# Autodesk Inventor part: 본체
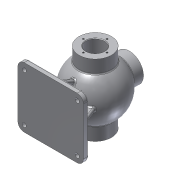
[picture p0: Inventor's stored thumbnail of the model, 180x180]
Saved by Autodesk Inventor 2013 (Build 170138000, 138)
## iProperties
Created: 2018-06
Part Number: 본체
Material: 알루미늄 6061
Document SubType Name: Modeling
Designer: Administrator
Density: 2.71 g/cm^3
Mass: 1509.59 g
Surface Area: 1153.86 cm^2
Volume: 557.044 cm^3
Author: Administrator
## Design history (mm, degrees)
sketch "스케치2"
  geometry: L1 (0, 103.075)-(0, -103.075); A1 r 53 centre (0, 0) between (0, -53) and (0, 53); 2 further points
  constraints: 2 coincident, 2 end point, 2 point on circle, 2 point on line, 1 centre point, 1 midpoint, 1 vertical
  dimensions: "d0" = 106 diameter of A1
revolve "회전1" sketch "스케치2" stored, may be unused: angle "d1" = 90 deg
node "작업 평면1"
sketch "스케치4"
  geometry: C1 r 31 at (0, 0); 1 further point
  constraints: 1 centre point, 1 coincident
  dimensions: "d3" = 62 diameter of C1
extrude "돌출1" join sketch "스케치4" distance "d4" = 136; taper "d5" = 0 deg
sketch "스케치5"
  geometry: L1 (0, -49.435)-(0, 49.435); A1 r 43 centre (0, 0) between (0, -43) and (0, 43); 2 further points
  constraints: 2 coincident, 2 end point, 2 point on circle, 2 point on line, 1 centre point, 1 midpoint, 1 vertical
  dimensions: "d6" = 86 diameter of A1
revolve "회전2" sketch "스케치5" stored, may be unused: angle "d7" = 90 deg
sketch "스케치6"
  geometry: C1 r 31 at (0, 0) reference; C2 r 17.5 at (0, 0)
  constraints: 1 centre point, 1 coincident
  dimensions: "d8" = 35 diameter of C2
extrude "돌출2" cut sketch "스케치6" stored distance "d9" = 136; taper "d10" = 0 deg
node "작업 평면2"
sketch "스케치7"
  geometry: L1 (62.5, -57.5)-(-62.5, -57.5); L2 (-62.5, -57.5)-(-62.5, 57.5); L3 (-62.5, 57.5)-(62.5, 57.5); L4 (62.5, 57.5)-(62.5, -57.5); L5 (62.5, -57.5)-(-62.5, 57.5); L6 (-62.5, -57.5)-(62.5, 57.5); 1 further point
  constraints: 12 end point, 2 midpoint, 2 parallel, 1 horizontal, 1 perpendicular
  dimensions: "d12" = 125 distance of L2.end L3.end; "d13" = 115 distance of L1.end L2.end
extrude "돌출3" join sketch "스케치7" distance "d14" = 10; taper "d15" = 0 deg
fillet "모깎기1" dims "d16" = 12
sketch "스케치8"
  geometry: L1 (-31.053, 29.744)-(-75, 47.5); L2 (-75, 47.5)-(-75, -47.5); L3 (-75, -47.5)-(-31.053, -29.744); L4 (-75, -57.5)-(-85, -57.5) reference; L5 (-85, 57.5)-(-75, 57.5) reference; L6 (-75, -45.5)-(-75, 45.5) reference; A1 r 43 centre (0, 0) between (-31.053, 29.744) and (-31.053, -29.744); 2 further points
  constraints: 6 end point, 2 midpoint, 2 point on circle, 1 centre point, 1 coincident, 1 vertical
  dimensions: "d18" = 86 diameter of A1; "d20" = 10 distance from line of L4 L2.end; "d21" = 10 distance from line of L5 L1.end; "d22" = 22 deg angle of L5 L1; "d23" = 22 deg angle of L4 L3
extrude "돌출4" join sketch "스케치8" stored distance "d24" = 8; taper "d25" = 0 deg
sketch "스케치9"
  geometry: L1 (-52.5, -75)-(-42.423, -50.06); L2 (-62.5, -75)-(-62.5, -85) reference; L3 (-50.5, -75)-(50.5, -75) reference; 1 further point
  constraints: 2 end point, 1 point on line
  dimensions: "d26" = 10 distance from line of L2 L1.start; "d27" = 22 deg angle of L2 L1
feature "리브1" sketch "스케치9" dims "d28" = 1, "d29" = 8, "d30" = 0, "d31" = 0, "d32" = 1, "d33" = 1
node "작업 평면3"
sketch "스케치11"
  geometry: C1 r 27 at (0, 0); 1 further point
  constraints: 1 centre point, 1 coincident
  dimensions: "d44" = 54 diameter of C1
extrude "돌출5" join sketch "스케치11" stored distance "d45" = 8; taper "d46" = 0 deg
sketch "스케치12"
  geometry: C1 r 27 at (0, 0) reference; C2 r 13 at (0, 0)
  constraints: 1 centre point, 1 coincident
  dimensions: "d47" = 26 diameter of C2
extrude "돌출6" cut sketch "스케치12" stored distance "d48" = 8; taper "d49" = 0 deg
sketch "스케치13"
  geometry: L1 (18.5, -50.25)-(0, -50.25); L2 (0, -50.25)-(0, -52); L3 (0, -52)-(18.5, -52); L4 (18.5, -52)-(18.5, -50.25); L5 (17.5, -68)-(-17.5, -68) reference; 2 further points
  constraints: 8 end point, 2 parallel, 1 horizontal, 1 midpoint, 1 perpendicular, 1 vertical alignment
  dimensions: "d50" = 1.75 distance of L1.end L2.end; "d52" = 16 distance between parallel lines of L5 L3; "d54" = 37 diameter of L4 L2
revolve "회전3" sketch "스케치13" stored, may be unused: angle "d55" = 90 deg
sketch "스케치14"
  geometry: C1 r 17.5 at (0, 0) reference; 1 further point
  constraints: 1 vertical alignment
  dimensions: "d56" = 22.5 distance of C1.centre point (0, 22.5)
hole "구멍2" sketch "스케치14" at (0, 22.5) diameter "d57" = 3.242; stored, may be unused: countersink angle "d61" = 90 deg, drill point angle "d63" = 118 deg; dims "d58" = 12, "d59" = 12, "d60" = 3, "d62" = 15
sketch "스케치15"
  geometry: C1 r 17.5 at (0, 0) reference; 1 further point
  constraints: 1 vertical alignment
  dimensions: "d67" = 24 distance of C1.centre point (0, 24)
hole "구멍3" sketch "스케치15" at (0, 24) diameter "d68" = 3.242; stored, may be unused: countersink angle "d72" = 90 deg, drill point angle "d74" = 118 deg; dims "d69" = 16, "d70" = 12, "d71" = 3, "d73" = 19
sketch "스케치16"
  geometry: C1 r 13 at (0, 0) reference; 1 further point
  constraints: 1 vertical alignment
  dimensions: "d78" = 20 distance of C1.centre point (0, 20)
hole "구멍4" sketch "스케치16" at (0, 20) diameter "d79" = 3.242; stored, may be unused: countersink angle "d83" = 90 deg, drill point angle "d85" = 118 deg; dims "d80" = 9, "d81" = 12, "d82" = 3, "d84" = 11
node "작업 평면4"
sketch "스케치18"
  geometry: 2 further points
  dimensions: "d94" = 50.5 horizontal distance of point (-50.5, 45.5) point (0, 0); "d95" = 45.5 vertical distance of point (0, 0) point (-50.5, 45.5)
hole "구멍5" sketch "스케치18" at (-50.5, 45.5) diameter "d96" = 8; stored, may be unused: countersink angle "d100" = 90 deg, drill point angle "d102" = 118 deg; dims "d97" = 9, "d98" = 12, "d99" = 3, "d101" = 11
chamfer "모따기1" distance "d103" = 1; stored, may be unused: second distance "d104" = 2, angle "d105" = 45 deg
fillet "모깎기3" dims "d107" = 3, "d108" = 3
fillet "모깎기4" dims "d109" = 3
node "작업 평면5"
sketch "스케치20"
  geometry: L1 (-65, -27)-(-47.286, -27) reference; L2 (-65, -27)-(-65, 27) reference; 2 further points
  constraints: 1 other
  dimensions: "d111" = 27 distance from line of L1 point (-55, 0); "d112" = 10 distance from line of L2 point (-55, 0)
feature "엠보싱2" sketch "스케치20" dims "d113" = 0.5, "d114" = 0
node "솔리드1"
mirror "대칭1"
pattern_circular "원형 패턴1" dims angle "d65" = 360 deg
pattern_circular "원형 패턴2" dims angle "d76" = 360 deg
pattern_circular "원형 패턴3" dims angle "d87" = 360 deg
mirror "대칭4"
mirror "대칭5"
other parameters: "d2" = 68, "d11" = -85, "d89" = 27.5, "d110" = -27.5
